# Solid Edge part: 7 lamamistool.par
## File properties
Author: Henri
Template: Normal.par
Last saved by: Henri
Revision: 1
Application: Solid Edge
Accuracy: 0,990
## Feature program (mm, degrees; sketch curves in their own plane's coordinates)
sketch for "unnamed Protrusion 1" plane through (0, 0, 0) normal (0, 0, 1) x-axis (1, 0, 0)
  line (50, -25) -> (-50, -25)
  line (-50, -25) -> (-50, 25)
  line (-50, 25) -> (50, 25)
  line (50, 25) -> (50, -25)
extrude "unnamed Protrusion 1" add finite 25 along +normal
replace surface "unnamed ReplaceSurface 1"
replace surface "unnamed ReplaceSurface 2"
thinwall "Thinwall_3"  Thickness = 4 mm
fillet "Round_1" radius 0.3
sketch for "unnamed Protrusion 2" #1 plane through (0, 0, -10) normal (0, 0, 1) x-axis (1, 0, 0)
  circle centre (-45, -20) radius 1.75
sketch for "unnamed Protrusion 2" #2 plane through (0, 0, -10) normal (0, 0, 1) x-axis (1, 0, 0)
  circle centre (-45, 20) radius 1.75
sketch for "unnamed Protrusion 2" #3 plane through (0, 0, -10) normal (0, 0, 1) x-axis (1, 0, 0)
  circle centre (45, -20) radius 1.75
sketch for "unnamed Protrusion 2" #4 plane through (0, 0, -10) normal (0, 0, 1) x-axis (1, 0, 0)
  circle centre (45, 20) radius 1.75
extrude "unnamed Protrusion 2" add through along +normal
fillet "Round_3" radius 2
Other named dimensions: "ExtrudedSurface_1": FiniteDepth = 50 mm | "ExtrudedSurface_2": FiniteDepth = 50 mm
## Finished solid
Body 1: sheet body, 2 faces, 7 edges, 6 vertices.
  Faces by surface: cylinder 2
  Edges by curve: circle 4, line 3
Body 2: sheet body, 2 faces, 7 edges, 6 vertices.
  Faces by surface: cylinder 2
  Edges by curve: circle 4, line 3
Body 3: solid body, 46 faces, 108 edges, 64 vertices.
  Faces by surface: cylinder 18, torus 16, plane 12
  Edges by curve: circle 44, intersection 38, line 26
Bounding box of the edges (mm; curved faces can reach further): 108.559 x 50.000 x 34.710, from (-55.2236, -25, -10) to (53.3358, 25, 24.7097).
Cylindrical faces by radius (mm): R0.3 x4, R1.75 x4, R2 x4, R52.1808 x2, R56.1808 x1, R57.1808 x2, R62.752 x2, R63.752 x1, R67.752 x2
Toroidal faces (ring radius, tube radius in mm): R54.1808 r2 x2, R55.1808 r2 x2, R56.4808 r0.3 x2, R56.8808 r0.3 x2, R63.052 r0.3 x2, R63.452 r0.3 x2, R64.752 r2 x2, R65.752 r2 x2
Planar faces by outward normal: +x 2, +y 2, -x 2, -y 2, -z 4
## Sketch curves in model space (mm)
circle centre (45, -20, -10) radius 1.75
circle centre (45, 20, -10) radius 1.75
circle centre (-45, -20, -10) radius 1.75
circle centre (-45, 20, -10) radius 1.75
line (45, 20, -10) -> (45, -20, -10)
line (45, -20, -10) -> (-45, -20, -10)
line (-45, -20, -10) -> (-45, 20, -10)
line (-45, 20, -10) -> (45, 20, -10)
arc centre (32.2444, -25, -44.7882) radius 52.1808 from (14.95, -25, 4.4433) through (34.2863, -25, 7.3527) to (53.3358, -25, 2.9401)
arc centre (-6.8078, -25, 68.6067) radius 67.752 from (-55.2236, -25, 21.212) through (-22.5545, -25, 2.7099) to (14.95, -25, 4.4433)
arc centre (32.2444, -25, -44.7882) radius 57.1808 from (13.3196, -25, 9.1701) through (32.2444, -25, 12.3926) to (51.1693, -25, 9.1701)
arc centre (-6.8078, -25, 68.6067) radius 62.752 from (-51.6506, -25, 24.7097) through (-21.4051, -25, 7.576) to (13.3196, -25, 9.1701)
line (50, 25, 0) -> (50, -25, 0)
line (50, -25, 0) -> (-50, -25, 0)
line (-50, -25, 0) -> (-50, 25, 0)
line (-50, 25, 0) -> (50, 25, 0)
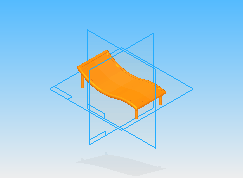
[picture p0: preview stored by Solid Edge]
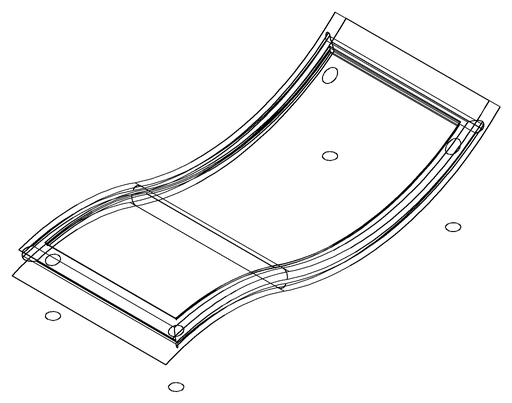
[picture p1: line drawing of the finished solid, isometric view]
